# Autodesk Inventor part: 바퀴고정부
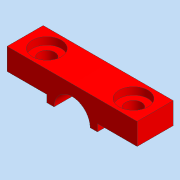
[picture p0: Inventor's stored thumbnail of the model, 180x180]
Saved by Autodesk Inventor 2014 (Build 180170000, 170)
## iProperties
Company: 한국ATC센터
Created: 2015-05
Part Number: 바퀴고정부
Document SubType Name: 모델링
Designer: KYOUNG IL JANG
Vendor: CBT Solutions
Material: 일반
Appearance: 기본값
d0: 1.000 ul
Author: KYOUNG IL JANG
Comments: 파생
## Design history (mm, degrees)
derived "바퀴고정부.ipt" dims count "d0" = 1
node "솔리드1"
node "솔리드 본체"
node "곡면 본체"
feature "솔리드1::바퀴고정부.ipt" dims count "d0" = 1
tag "피쳐 태그1"
